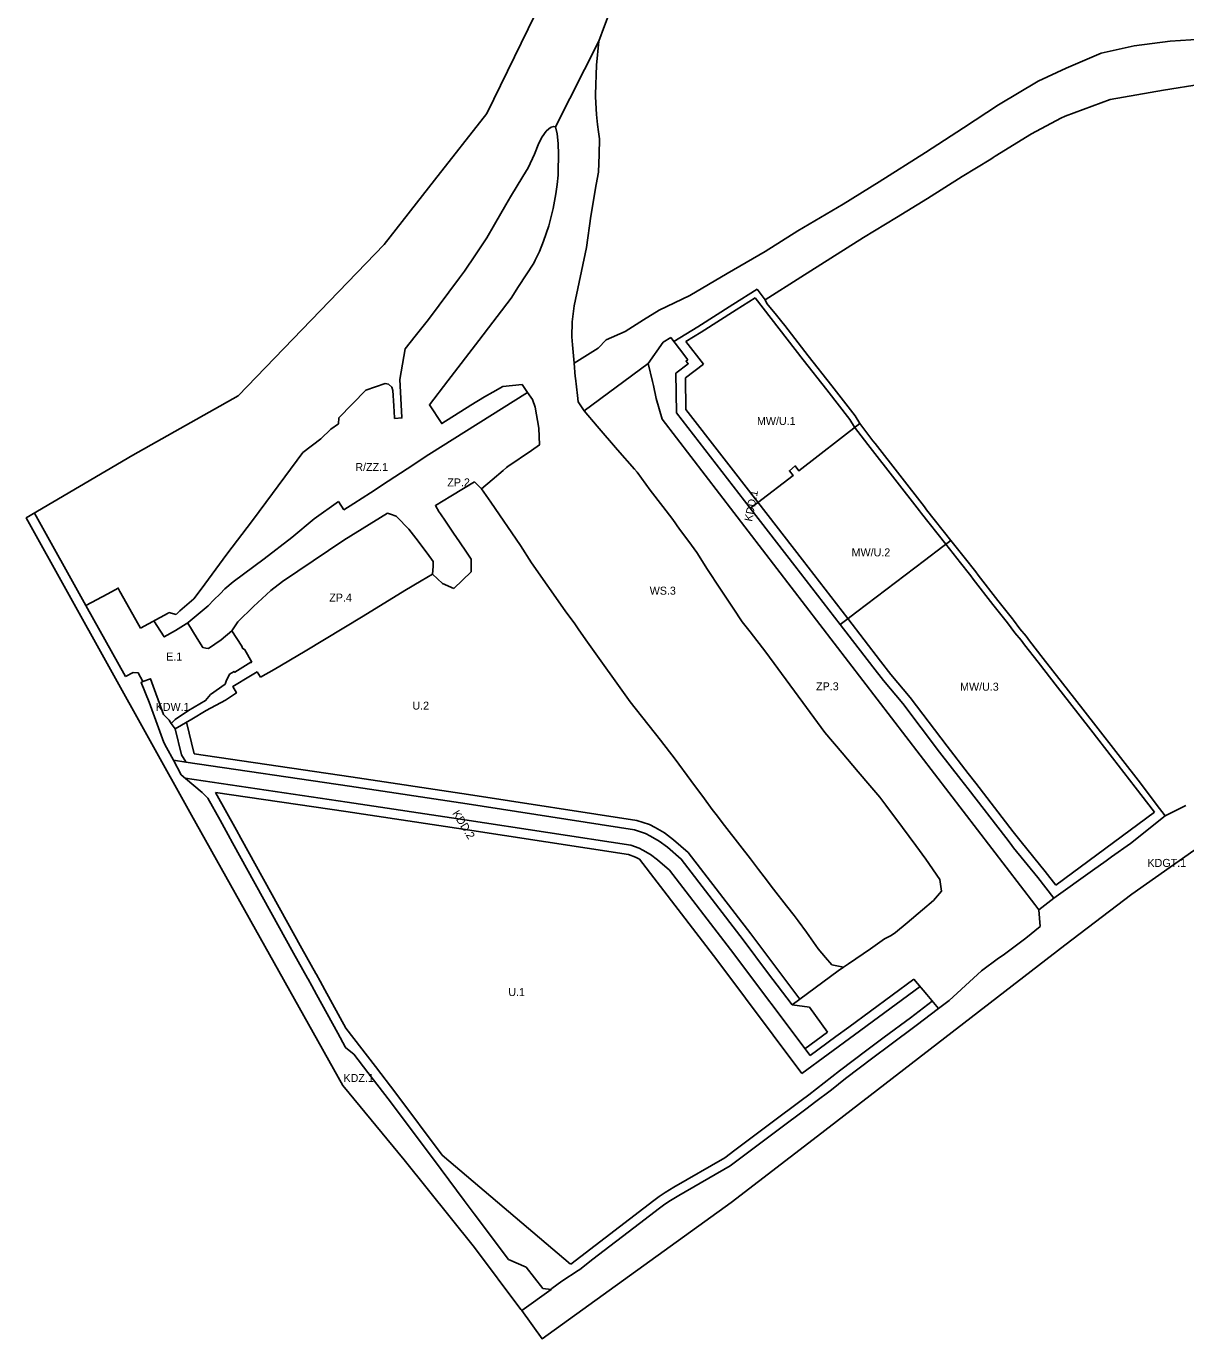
# Model space of a CAD drawing. Extents: x 7426626 to 7428617, y 5546366 to 5547802.
# Drawn here: x 7426751 to 7427476, y 5546366 to 5547186 of the extents above; entities that cross this region are included whole.
import ezdxf

# ---------------------------------------------------------------- set-up
doc = ezdxf.new("R2010")
doc.units = 0
for name, color, linetype in [('LIN_Linia Zabudowy Nieprzekraczalna', 7, 'Continuous'), ('LIN_Linie Rozgraniczajace', 7, 'Continuous'), ('TXT_Oznaczenia Przeznaczenia', 7, 'Continuous')]:
    doc.layers.add(name, color=color, linetype=linetype)

msp = doc.modelspace()

# ---------------------------------------------------------------- linework, layer by layer
at = {"layer": 'LIN_Linia Zabudowy Nieprzekraczalna'}
for p, q in [((7427163.52, 5546946.79), (7427208.41, 5546888.73)), ((7427208.41, 5546888.73), (7427236.28, 5546852.69)), ((7427236.28, 5546852.69), (7427264.61, 5546816.04)), ((7427264.61, 5546816.04), (7427285.11, 5546789.5)), ((7427285.11, 5546789.5), (7427291.55, 5546781.18)), ((7427291.55, 5546781.18), (7427303.67, 5546766.67)), ((7427303.67, 5546766.67), (7427326.68, 5546736.3)), ((7426851.4, 5546751.33), (7426856.24, 5546731.62)), ((7427326.68, 5546736.3), (7427339.95, 5546719.2)), ((7427394.6, 5546649.5), (7427456.19, 5546695.03)), ((7427011.23, 5546480.79), (7427091.36, 5546412.68))]:
    msp.add_line(p, q, dxfattribs=at)
for points in [[(7427206.8, 5547016.48), (7427194.93, 5547008.94), (7427173, 5546995.01), (7427163.47, 5546989.13)], [(7427268.88, 5546935.56), (7427265.87, 5546940.38), (7427251.52, 5546958.93), (7427236.78, 5546977.83), (7427206.8, 5547016.48)], [(7427163.47, 5546989.13), (7427174.44, 5546975.02)], [(7427174.44, 5546975.02), (7427163.25, 5546966.46), (7427163.52, 5546946.79)], [(7427325.98, 5546862.44), (7427310.72, 5546881.63), (7427309.37, 5546883.41), (7427278.55, 5546922.93), (7427277.19, 5546924.75), (7427268.88, 5546935.56)], [(7427364.41, 5546813.47), (7427355.35, 5546824.82), (7427343.03, 5546840.68), (7427341.42, 5546842.8), (7427340.66, 5546843.77), (7427335.07, 5546850.88), (7427325.98, 5546862.44)], [(7427403.09, 5546763.67), (7427395.73, 5546773.15), (7427383.54, 5546788.71), (7427375.12, 5546799.68), (7427372.93, 5546802.48), (7427369.06, 5546807.23), (7427364.41, 5546813.47)], [(7427430, 5546729.12), (7427416.44, 5546746.52), (7427403.09, 5546763.67)], [(7426856.24, 5546731.62), (7426954.16, 5546717.23), (7427027.68, 5546706.17), (7427132.81, 5546689.96), (7427140.64, 5546687.33), (7427144.3, 5546685.42), (7427150.06, 5546682.07), (7427155.79, 5546677.86), (7427164.94, 5546669.83), (7427203.98, 5546618.97), (7427234.57, 5546578.2)], [(7427456.19, 5546695.03), (7427444.27, 5546710.72), (7427430, 5546729.12)], [(7427339.95, 5546719.2), (7427344.56, 5546713.26), (7427368.04, 5546682.83), (7427372.97, 5546676.44), (7427388.05, 5546658.06), (7427394.6, 5546649.5)], [(7426869.61, 5546707.42), (7426882.61, 5546683.89), (7426885.44, 5546678.77), (7426923.56, 5546609.78), (7426932.15, 5546594.35), (7426932.56, 5546593.63), (7426934.86, 5546589.5), (7426937.92, 5546584.01), (7426950.95, 5546560.19)], [(7427134.39, 5546665.78), (7427132, 5546667.02), (7427127.59, 5546668.51), (7427024.36, 5546684.43), (7426950.92, 5546695.47), (7426869.61, 5546707.42)], [(7427236, 5546531.82), (7427182.71, 5546602.83), (7427134.39, 5546665.78)], [(7427309.88, 5546586.06), (7427268.78, 5546555.89), (7427236, 5546531.82)], [(7427187.78, 5546479.01), (7427194.12, 5546483.86), (7427217.42, 5546501.34), (7427235.57, 5546514.92), (7427240.3, 5546518.47), (7427259.48, 5546533.4), (7427276.57, 5546546.29), (7427287.29, 5546554.37), (7427303.77, 5546566.54), (7427317.42, 5546577.04)], [(7426950.95, 5546560.19), (7426969.52, 5546536.07), (7426982.28, 5546519.5), (7427011.23, 5546480.79)], [(7427091.46, 5546412.59), (7427143.39, 5546452.42), (7427146.76, 5546454.91), (7427150.52, 5546457.47), (7427155.93, 5546460.77), (7427187.78, 5546479.01)]]:
    msp.add_lwpolyline(points, dxfattribs=at)
at = {"layer": 'LIN_Linie Rozgraniczajace'}
for p, q in [((7427109.04, 5547176.91), (7427081.96, 5547123.28)), ((7427039.12, 5547131.71), (7427006.42, 5547090.08)), ((7427077.81, 5547122.17), (7427076.13, 5547120.61)), ((7427068.9, 5547106.17), (7427065, 5547097.75)), ((7427061.53, 5547092.29), (7427053.81, 5547079.65)), ((7427065, 5547097.75), (7427061.53, 5547092.29)), ((7427006.42, 5547090.08), (7426974.85, 5547049.86)), ((7427053.81, 5547079.65), (7427050.88, 5547074.55)), ((7427050.88, 5547074.55), (7427043.96, 5547062.37)), ((7427022.08, 5547028.91), (7427002.71, 5547002.92)), ((7427207.9, 5547021.91), (7427213.04, 5547015.13)), ((7427165.88, 5547017.92), (7427146.66, 5547008.84)), ((7427220.1, 5547005.54), (7427223.42, 5547001.47)), ((7427223.42, 5547001.47), (7427225.34, 5546999.11)), ((7427225.34, 5546999.11), (7427239.94, 5546980.29)), ((7427093.65, 5546975.6), (7427108.54, 5546984.94)), ((7427239.94, 5546980.29), (7427254.68, 5546961.38)), ((7427093.65, 5546975.6), (7427094.36, 5546967.21)), ((7427099.82, 5546945.84), (7427139.98, 5546975.42)), ((7426975.49, 5546962.94), (7426963.52, 5546958.68)), ((7427064.57, 5546957.35), (7427061.1, 5546962.29)), ((7427094.36, 5546967.21), (7427094.44, 5546966.24)), ((7426963.52, 5546958.68), (7426946.55, 5546941.55)), ((7427002.75, 5546918.57), (7427064.57, 5546957.35)), ((7426946.39, 5546937.67), (7426941.64, 5546934.35)), ((7426946.55, 5546941.55), (7426946.39, 5546937.67)), ((7426981.45, 5546941.15), (7426981.4, 5546941.47)), ((7427272.17, 5546937.84), (7427280.37, 5546927.17)), ((7426941.64, 5546934.35), (7426935.3, 5546928.42)), ((7427035.74, 5546897.15), (7427031.27, 5546901.54)), ((7426946.47, 5546889.11), (7426949.79, 5546883.93)), ((7427313.88, 5546884.08), (7427329.12, 5546864.92)), ((7427329.12, 5546864.92), (7427338.22, 5546853.35)), ((7427005.54, 5546848.59), (7427005.16, 5546843.83)), ((7427005.16, 5546843.83), (7427011.35, 5546837.97)), ((7427011.35, 5546837.97), (7427018.49, 5546834.79)), ((7426839.89, 5546819.5), (7426822.7, 5546810.03)), ((7426851.28, 5546812.68), (7426852.17, 5546813.4)), ((7426852.26, 5546813.25), (7426852.17, 5546813.4)), ((7427376.06, 5546804.97), (7427378.28, 5546802.13)), ((7427378.28, 5546802.13), (7427386.7, 5546791.16)), ((7427406.25, 5546766.13), (7427419.6, 5546748.98)), ((7426850.93, 5546726.44), (7426851, 5546726.33)), ((7427457.35, 5546700.11), (7427463.06, 5546692.82)), ((7427463.06, 5546692.82), (7427475.93, 5546699.23)), ((7427245.64, 5546492.63), (7427400.2, 5546611.86)), ((7427240.63, 5546573.31), (7427229.77, 5546574.6)), ((7427251.89, 5546557.57), (7427240.63, 5546573.31)), ((7426949.02, 5546524.25), (7426987.38, 5546477.9)), ((7427079.19, 5546396.89), (7427060.86, 5546383.69))]:
    msp.add_line(p, q, dxfattribs=at)
for points in [[(7427115.61, 5547285.85), (7427090.72, 5547237.61), (7427039.12, 5547131.71)], [(7427093.65, 5546975.6), (7427092.69, 5546987), (7427092.13, 5546992.12), (7427092.33, 5547001.52), (7427093.55, 5547011.38), (7427101.25, 5547047.95), (7427104.16, 5547067.46), (7427107.47, 5547087.27), (7427108.87, 5547095.08), (7427109.25, 5547106.05), (7427109.5, 5547115.74), (7427108.94, 5547120.23), (7427108.32, 5547124.78), (7427107.58, 5547130.97), (7427107, 5547142.13), (7427107.06, 5547143.62), (7427107.63, 5547161.87), (7427109.04, 5547176.91), (7427112.56, 5547186.38), (7427115.56, 5547194.07), (7427118.07, 5547199.79), (7427122.92, 5547209.49), (7427128.08, 5547219.77)], [(7427165.88, 5547017.92), (7427189.27, 5547031.72), (7427212.98, 5547045.35), (7427233.31, 5547058.28), (7427261.82, 5547075.07), (7427284.33, 5547089.02), (7427313.27, 5547107.33), (7427336.96, 5547122.74), (7427358.71, 5547137.11), (7427383.6, 5547151.95), (7427401.18, 5547159.94), (7427422.99, 5547169.37), (7427443.68, 5547173.93), (7427466.15, 5547176.95), (7427485.41, 5547178.13), (7427512.52, 5547176.96), (7427536.38, 5547175.21), (7427556.35, 5547172.06), (7427560.68, 5547171.39), (7427568.03, 5547168.57), (7427581.85, 5547162.89)], [(7427485.47, 5547149.96), (7427461.93, 5547146.24), (7427428.55, 5547140.45), (7427400.48, 5547129.92), (7427397.76, 5547128.68), (7427379.43, 5547118.99), (7427356.67, 5547105.08), (7427355.52, 5547104.24), (7427353.96, 5547103.12), (7427336.03, 5547092.23), (7427314.44, 5547078.63), (7427295.01, 5547066.73), (7427274.53, 5547054.13), (7427254.12, 5547041.31), (7427235.33, 5547029.4), (7427213.04, 5547015.13)], [(7427076.13, 5547120.61), (7427073.65, 5547117.03), (7427071.59, 5547113.17), (7427068.9, 5547106.17)], [(7427083.82, 5547106.13), (7427083.63, 5547112.81), (7427083.02, 5547118.85), (7427081.96, 5547123.28), (7427080.89, 5547123.57), (7427079.32, 5547123.21), (7427077.81, 5547122.17)], [(7427082.99, 5547087.19), (7427083.58, 5547093.13), (7427083.74, 5547095.45), (7427083.82, 5547106.13)], [(7427080.44, 5547072.26), (7427082.18, 5547081.38), (7427082.99, 5547087.19)], [(7427074.55, 5547051.92), (7427077.79, 5547061.51), (7427080.44, 5547072.26)], [(7427043.96, 5547062.37), (7427039.08, 5547053.96), (7427031.94, 5547043.25)], [(7427069.37, 5547039.92), (7427071.96, 5547045.52), (7427074.55, 5547051.92)], [(7426974.85, 5547049.86), (7426883.67, 5546955.21), (7426817.87, 5546918.13), (7426751.25, 5546878.91), (7426854.57, 5546693.24), (7426949.02, 5546524.25)], [(7427031.94, 5547043.25), (7427025.19, 5547033.12), (7427022.08, 5547028.91)], [(7427029.13, 5546949.33), (7427010.94, 5546937.91), (7427003.14, 5546949.7), (7427014.72, 5546964.62), (7427034.16, 5546989.77), (7427054.33, 5547016.22), (7427058.94, 5547023.54), (7427068.34, 5547038.23), (7427069.37, 5547039.92)], [(7427400.2, 5546611.86), (7427442.19, 5546643.82), (7427480.94, 5546671.03), (7427524.86, 5546698.24), (7427615.03, 5546744.99), (7427747.54, 5546812.47), (7427897.12, 5546887.45), (7428084.42, 5546980.69), (7428179.45, 5547028.08)], [(7427207.9, 5547021.91), (7427192.79, 5547012.32), (7427170.88, 5546998.4), (7427155.87, 5546989.14)], [(7427213.04, 5547015.13), (7427214.08, 5547012.94), (7427220.1, 5547005.54)], [(7427002.71, 5547002.92), (7426994.33, 5546992.6), (7426988.12, 5546984.63)], [(7427108.54, 5546984.94), (7427113.66, 5546990.13), (7427125.55, 5546995.37), (7427136.89, 5547002.66)], [(7427146.66, 5547008.84), (7427136.89, 5547002.66)], [(7427384.09, 5546634.08), (7427381.51, 5546637.43), (7427148.61, 5546940.65), (7427146.74, 5546947.2), (7427144.96, 5546953.6), (7427143.13, 5546961.62), (7427142.55, 5546964.17), (7427139.98, 5546975.42), (7427149.17, 5546988.71), (7427153.96, 5546991.61)], [(7427153.96, 5546991.61), (7427159.46, 5546984.51), (7427164.68, 5546977.8)], [(7426988.12, 5546984.63), (7426984.73, 5546965.36), (7426986.05, 5546941.74)], [(7427164.68, 5546977.8), (7427163.62, 5546976.94), (7427164.92, 5546975.29), (7427157.21, 5546969.39), (7427157.54, 5546944.7)], [(7426980.33, 5546958.47), (7426979.73, 5546960.57), (7426977.67, 5546962.46), (7426975.49, 5546962.94)], [(7427061.1, 5546962.29), (7427049, 5546961.12), (7427042.92, 5546957.62)], [(7427094.44, 5546966.24), (7427095.76, 5546955.43)], [(7427254.68, 5546961.38), (7427269.16, 5546942.67), (7427272.17, 5546937.84)], [(7426981.4, 5546941.47), (7426980.98, 5546948.97), (7426980.33, 5546958.47)], [(7427042.92, 5546957.62), (7427037.54, 5546954.53), (7427029.13, 5546949.33)], [(7427069.29, 5546948.24), (7427067.66, 5546952.96), (7427064.57, 5546957.35)], [(7427095.76, 5546955.43), (7427096.24, 5546951.51), (7427099.82, 5546945.84)], [(7427069.29, 5546948.24), (7427071.62, 5546935.03), (7427071.97, 5546924.55), (7427066.91, 5546921.1)], [(7427099.82, 5546945.84), (7427108.02, 5546936.3), (7427120.71, 5546921.57), (7427131.29, 5546909.37), (7427132.93, 5546907.52), (7427141.21, 5546896.25), (7427149.14, 5546886.14), (7427155.21, 5546877.85), (7427159.56, 5546871.99), (7427165.33, 5546864.17), (7427170.28, 5546857.34), (7427176.92, 5546846.75), (7427184.59, 5546834.97), (7427193.01, 5546822.51), (7427198.65, 5546814.07), (7427203.7, 5546807.68), (7427213.33, 5546794.99), (7427220.99, 5546784.9), (7427238.79, 5546760.51), (7427250.18, 5546744.84), (7427261.02, 5546732.12), (7427271.16, 5546720.27), (7427278.44, 5546711.75), (7427284.62, 5546704.42), (7427288.32, 5546699.45), (7427298.88, 5546685.48), (7427307.14, 5546674.31), (7427313.31, 5546665.68), (7427322.18, 5546652.92), (7427323.1, 5546645.79), (7427318.1, 5546639.88), (7427311.31, 5546634.05), (7427301.69, 5546625.91), (7427294.48, 5546619.77), (7427291.66, 5546617.91)], [(7427157.54, 5546944.7), (7427203.66, 5546885.06), (7427231.53, 5546849.02), (7427259.86, 5546812.37), (7427280.36, 5546785.83), (7427286.87, 5546777.42), (7427298.97, 5546762.93), (7427321.92, 5546732.65), (7427335.21, 5546715.52), (7427339.81, 5546709.59), (7427363.29, 5546679.16), (7427366.04, 5546675.6), (7427368.28, 5546672.7), (7427383.35, 5546654.33), (7427393.36, 5546641.24)], [(7426986.05, 5546941.74), (7426986.06, 5546941.43), (7426981.45, 5546941.15)], [(7427272.17, 5546937.84), (7427234.13, 5546908.35), (7427231.83, 5546911.39), (7427228.17, 5546908.45), (7427230.46, 5546905.4), (7427208.15, 5546888.47), (7427203.66, 5546885.06)], [(7426935.3, 5546928.42), (7426924.16, 5546919.84), (7426905.06, 5546894.1), (7426892.55, 5546877.39), (7426876.65, 5546856.38), (7426860.52, 5546834.34), (7426855.93, 5546828.37), (7426847.21, 5546820.95), (7426844.93, 5546818.52)], [(7427066.91, 5546921.1), (7427052.14, 5546911.16)], [(7427280.37, 5546927.17), (7427281.73, 5546925.36), (7427312.54, 5546885.85), (7427313.88, 5546884.08)], [(7426977.5, 5546901.95), (7426989.23, 5546909.68), (7427002.75, 5546918.57)], [(7427147.54, 5546740.16), (7427128.73, 5546764.02), (7427101.91, 5546801.38), (7427099.48, 5546804.81), (7427096.17, 5546809.54), (7427093.96, 5546812.72), (7427088.12, 5546820.97), (7427066.89, 5546850.84), (7427060.13, 5546861.76), (7427041.51, 5546888.71), (7427035.74, 5546897.15), (7427042.38, 5546902.76), (7427049.18, 5546908.53), (7427051.26, 5546910.38), (7427052.14, 5546911.16)], [(7426949.79, 5546883.93), (7426955.91, 5546887.85), (7426966.47, 5546894.64), (7426977.5, 5546901.95)], [(7427018.49, 5546834.79), (7427029.23, 5546845.35), (7427029.35, 5546853.11), (7427026.29, 5546857.55), (7427021.95, 5546863.96), (7427018.22, 5546869.43), (7427013.56, 5546876.31), (7427009.69, 5546882.02), (7427009.34, 5546882.62), (7427006.93, 5546886.7), (7427016.48, 5546892.58), (7427031.27, 5546901.54)], [(7426852.17, 5546813.4), (7426852.36, 5546813.55), (7426864.93, 5546824.01), (7426868.52, 5546827.7), (7426872.33, 5546831.56), (7426875.36, 5546834.56), (7426880.65, 5546838.91), (7426899.97, 5546853.39), (7426917.26, 5546866.72), (7426931.11, 5546878.46), (7426946.47, 5546889.11)], [(7426813.23, 5546779.79), (7426788.38, 5546824.13), (7426756.41, 5546881.95)], [(7426879.77, 5546808.42), (7426883.55, 5546813.98), (7426893.22, 5546823.49), (7426904.14, 5546833.63), (7426911.31, 5546839.3), (7426949.69, 5546864.97), (7426976.99, 5546881.89)], [(7426984.07, 5546878.42), (7426982.5, 5546880.1), (7426978.96, 5546881.19), (7426976.99, 5546881.89)], [(7427005.54, 5546848.59), (7427005.49, 5546851.73), (7427001.72, 5546856.89), (7426994.63, 5546866.31), (7426990.31, 5546872), (7426989.18, 5546873.21), (7426984.07, 5546878.42)], [(7427329.12, 5546864.92), (7427324.03, 5546861.06), (7427312.5, 5546852.31), (7427270.24, 5546820.25), (7427263.93, 5546815.46), (7427259.86, 5546812.37)], [(7427338.22, 5546853.35), (7427343.8, 5546846.24), (7427344.58, 5546845.25), (7427346.2, 5546843.12)], [(7427005.16, 5546843.83), (7426997.94, 5546839.54), (7426987.77, 5546833.5), (7426961.87, 5546817.62), (7426925.51, 5546795.69), (7426906.2, 5546784.19), (7426897.68, 5546779.44)], [(7427346.2, 5546843.12), (7427358.49, 5546827.29), (7427367.57, 5546815.92)], [(7426822.7, 5546810.03), (7426822.7, 5546810.03), (7426810.36, 5546831.93), (7426809.82, 5546832.89), (7426808.79, 5546835.12), (7426802.26, 5546831.6), (7426788.38, 5546824.13)], [(7426830.89, 5546814.54), (7426835.1, 5546808.13), (7426837.46, 5546804.56), (7426844.42, 5546808.67), (7426851.28, 5546812.68)], [(7426844.93, 5546818.52), (7426840.41, 5546819.75), (7426839.89, 5546819.5)], [(7427367.57, 5546815.92), (7427368.16, 5546815.13), (7427372.22, 5546809.69), (7427376.06, 5546804.97)], [(7426858.07, 5546803.57), (7426852.26, 5546813.25)], [(7426892.27, 5546788.8), (7426887.92, 5546796.55), (7426886.44, 5546797.49), (7426886.06, 5546798.87), (7426879.77, 5546808.42), (7426873.14, 5546802.75), (7426865.21, 5546797.33), (7426863.52, 5546797.65), (7426861.51, 5546798.04), (7426858.07, 5546803.57)], [(7427386.7, 5546791.16), (7427398.88, 5546775.61), (7427406.25, 5546766.13)], [(7426813.23, 5546779.79), (7426818.11, 5546782.43), (7426821.26, 5546782.13), (7426824.1, 5546776.63), (7426828.84, 5546778.4), (7426837.11, 5546756.02), (7426840.52, 5546752.6)], [(7426841.84, 5546750.44), (7426844.22, 5546752.97), (7426852.72, 5546758.67), (7426863.36, 5546764.77), (7426866.39, 5546768.58), (7426875.48, 5546775.12), (7426876.25, 5546776.85), (7426878.22, 5546781.28), (7426881.13, 5546783.07), (7426881.49, 5546782.46), (7426891.62, 5546788.72), (7426891.77, 5546788.52), (7426892.27, 5546788.8)], [(7426844.29, 5546747.13), (7426854.71, 5546753.28), (7426863.7, 5546758.57), (7426875.86, 5546765.15), (7426882.56, 5546769.62), (7426880.24, 5546773.58), (7426891.28, 5546780.34), (7426895.64, 5546782.79)], [(7426897.68, 5546779.44), (7426895.64, 5546782.79)], [(7426851, 5546726.33), (7426843.21, 5546727.47), (7426838.92, 5546735.44), (7426837.16, 5546738.62), (7426828.13, 5546763.77), (7426822.96, 5546776.09), (7426824.1, 5546776.63)], [(7426841.84, 5546750.44), (7426840.52, 5546752.6)], [(7426841.84, 5546750.44), (7426844.29, 5546747.13), (7426848.28, 5546730.89)], [(7427419.6, 5546748.98), (7427433.55, 5546731.07), (7427434.96, 5546729.25), (7427447.44, 5546713.16), (7427457.35, 5546700.11)], [(7427265.01, 5546600.19), (7427261.96, 5546598.12), (7427254.69, 5546599.77), (7427250.74, 5546604.35), (7427246.12, 5546609.61), (7427238.74, 5546619.99), (7427233.59, 5546627.22), (7427231.06, 5546630.55), (7427226.43, 5546636.56), (7427218.3, 5546647.03), (7427212.38, 5546654.71), (7427208.85, 5546659.28), (7427203.79, 5546665.95), (7427197.13, 5546674.5), (7427187.69, 5546686.7), (7427182.36, 5546693.62), (7427179.91, 5546696.7), (7427175.03, 5546703.36), (7427166.56, 5546714.88), (7427156.69, 5546728.12), (7427147.54, 5546740.16)], [(7426850.76, 5546716.12), (7426848.1, 5546718.4), (7426843.21, 5546727.47)], [(7426848.28, 5546730.89), (7426850.93, 5546726.44)], [(7426851, 5546726.33), (7426953.27, 5546711.3), (7427026.77, 5546700.24), (7427079.08, 5546692.18), (7427131.39, 5546684.11), (7427138.28, 5546681.79), (7427141.41, 5546680.16), (7427146.76, 5546677.04), (7427152.03, 5546673.18), (7427160.54, 5546665.71), (7427179.87, 5546640.53), (7427199.2, 5546615.34), (7427214.49, 5546594.97), (7427229.77, 5546574.6)], [(7426850.58, 5546716.28), (7426951.8, 5546701.41), (7427025.27, 5546690.36), (7427129.01, 5546674.36), (7427134.36, 5546672.56), (7427136.58, 5546671.4), (7427141.28, 5546668.67), (7427145.76, 5546665.38), (7427153.2, 5546658.85), (7427191.24, 5546609.3), (7427241.02, 5546542.95)], [(7426850.76, 5546716.12), (7426861.18, 5546707.28), (7426864.78, 5546703.76), (7426872.36, 5546690.04), (7426877.36, 5546680.99), (7426880.19, 5546675.87), (7426918.31, 5546606.87), (7426926.92, 5546591.41), (7426927.33, 5546590.69), (7426929.62, 5546586.58), (7426932.67, 5546581.11), (7426945.9, 5546556.91), (7426950.48, 5546548.51), (7426950.88, 5546547.79), (7426955.95, 5546543.86), (7426964.77, 5546532.41), (7426977.5, 5546515.87), (7426993.22, 5546494.85), (7427010.54, 5546471.69), (7427024.96, 5546452.42), (7427031.24, 5546444.03)], [(7427384.77, 5546623.68), (7427384.09, 5546634.08), (7427393.36, 5546641.24), (7427417.56, 5546658.54), (7427426.04, 5546664.66), (7427429.36, 5546667.06), (7427441.24, 5546675.51), (7427463.06, 5546692.82)], [(7427191.11, 5546474.01), (7427197.74, 5546479.08), (7427221.02, 5546496.54), (7427239.17, 5546510.12), (7427243.9, 5546513.67), (7427254.35, 5546521.48), (7427263.18, 5546528.68), (7427280.18, 5546541.5), (7427290.88, 5546549.56), (7427307.38, 5546561.75), (7427321.22, 5546572.39), (7427328.08, 5546577.43), (7427343.28, 5546591.28), (7427348.24, 5546595.86), (7427358.78, 5546603.88), (7427361.65, 5546605.63), (7427375.79, 5546616.33), (7427384.77, 5546623.68)], [(7427291.66, 5546617.91), (7427287.66, 5546615.83), (7427278.86, 5546609.72), (7427269.75, 5546603.41), (7427265.01, 5546600.19)], [(7427261.96, 5546598.12), (7427258.68, 5546595.89), (7427229.77, 5546574.6)], [(7427305.98, 5546590.64), (7427265.23, 5546560.73), (7427257.22, 5546554.85)], [(7427305.98, 5546590.64), (7427314.06, 5546581.15), (7427321.22, 5546572.39)], [(7427251.89, 5546557.57), (7427237.81, 5546547.23)], [(7427257.22, 5546554.85), (7427241.02, 5546542.95)], [(7427060.86, 5546383.69), (7427073.59, 5546366.01), (7427191.84, 5546451.13), (7427245.64, 5546492.63)], [(7426987.38, 5546477.9), (7427031.31, 5546423.07), (7427060.39, 5546384.34), (7427060.86, 5546383.69)], [(7427191.11, 5546474.01), (7427158.98, 5546455.61), (7427153.78, 5546452.42), (7427150.23, 5546450.01), (7427146.99, 5546447.63), (7427134.39, 5546437.96), (7427105.36, 5546415.7), (7427097.11, 5546409.36), (7427096.09, 5546408.59), (7427085.95, 5546402.07), (7427079.75, 5546397.31)], [(7427031.24, 5546444.03), (7427052.62, 5546415.45), (7427063.56, 5546410.76)], [(7427063.56, 5546410.76), (7427074.06, 5546397.36)], [(7427074.06, 5546397.36), (7427079.19, 5546396.89)], [(7427079.75, 5546397.31), (7427079.45, 5546397.1), (7427079.19, 5546396.89)]]:
    msp.add_lwpolyline(points, dxfattribs=at)

# ---------------------------------------------------------------- texts
at = {"layer": 'TXT_Oznaczenia Przeznaczenia'}
for s, p in [('MW/U.1', (7427207.87, 5546937.01)), ('R/ZZ.1', (7426956.9, 5546908.25)), ('ZP.2', (7427014.37, 5546898.63)), ('MW/U.2', (7427267.02, 5546854.91)), ('ZP.4', (7426940.6, 5546826.66)), ('WS.3', (7427140.85, 5546830.97)), ('E.1', (7426838.71, 5546789.82)), ('ZP.3', (7427244.83, 5546771.22)), ('MW/U.3', (7427334.81, 5546770.98)), ('U.2', (7426992.56, 5546759.15)), ('KDW.1', (7426832.12, 5546758.38)), ('KDGT.1', (7427451.89, 5546660.85)), ('U.1', (7427052.49, 5546580.16)), ('KDZ.1', (7426949.5, 5546526.46))]:
    msp.add_text(s, height=5, dxfattribs=at).set_placement(p)
for s, rotation, p in [('KDD.1', 79.05381, (7427204.84, 5546876.4)), ('KDD.2', 301.95768, (7427017.28, 5546694.33))]:
    msp.add_text(s, height=5, rotation=rotation, dxfattribs=at).set_placement(p)

doc.saveas('drawing.dxf')
